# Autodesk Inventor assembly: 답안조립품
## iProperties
Created: 2015-01
Part Number: 답안조립품
Document SubType Name: Assembly
Designer: elite
Mass: 8617.72 g
Surface Area: 4424.24 cm^2
Volume: 1987.42 cm^3
Density: 4.33613 g/cm^3
Author: elite
